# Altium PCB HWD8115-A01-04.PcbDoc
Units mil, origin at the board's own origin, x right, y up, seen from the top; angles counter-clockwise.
Board outline 1289.56 x 3691.13 mil, 2 copper layers (TopLayer, BottomLayer); 72 components, 55 nets, 228 pads, 384 vias.
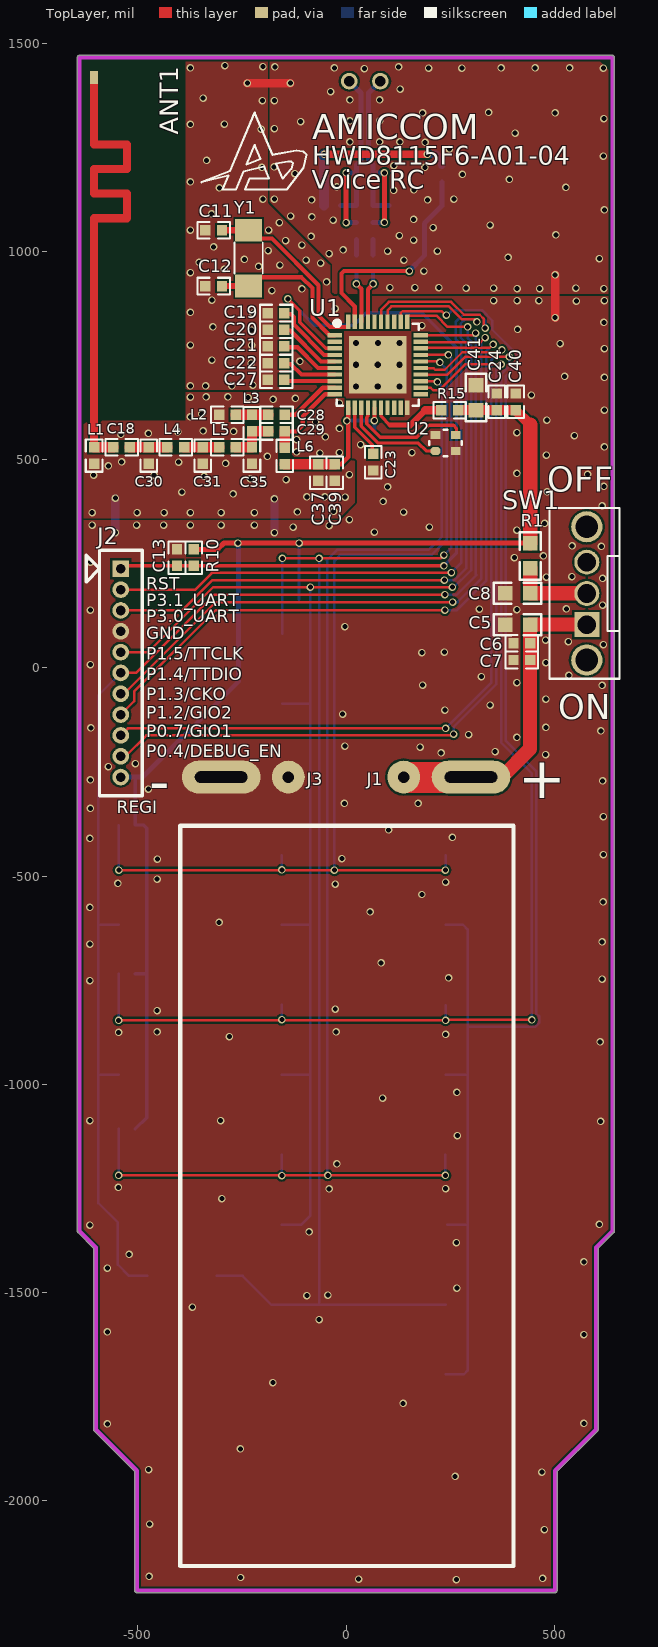
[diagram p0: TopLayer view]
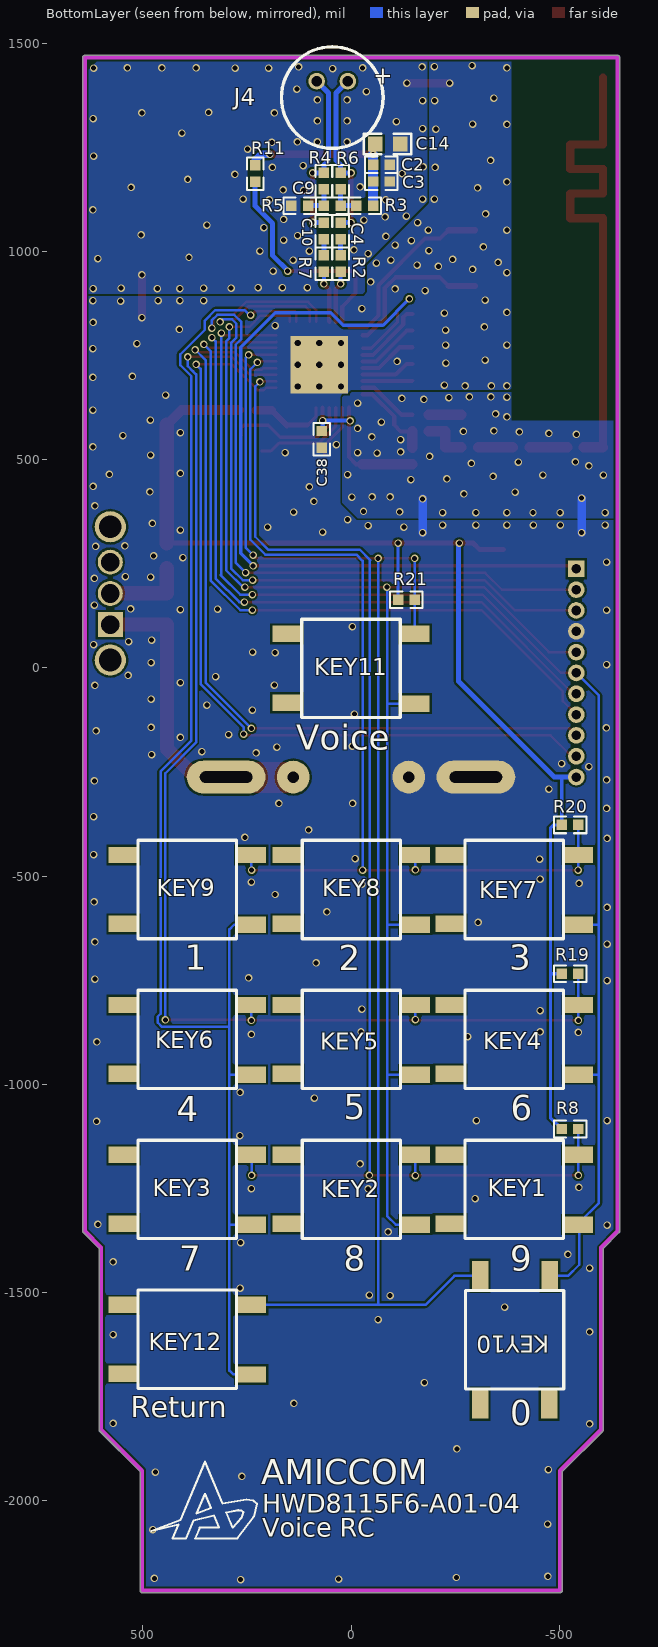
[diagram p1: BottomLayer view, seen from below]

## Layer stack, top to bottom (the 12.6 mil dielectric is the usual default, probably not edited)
TopSolder: solder mask 0.4, Solder Resist, Dk 3.5
TopLayer: signal copper 1.4
Dielectric1: dielectric 12.6, FR-4, Dk 4.8
BottomLayer: signal copper 1.4
BottomSolder: solder mask 0.4, Solder Resist, Dk 3.5

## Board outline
-507.38,-2215.27 -507.38,-1929.81 -604.33,-1832.85 -604.32,-1832.87 cw(c-600.79,-1829.3) -605.8,-1829.3 -605.8,-1393.74 -643.7,-1355.84 -643.69,-1355.85 cw(c-640.16,-1352.29) -645.17,-1352.29 -645.17,1465.83 cw(c-640.16,1465.83) -640.16,1470.85 639.37,1470.85 cw(c639.37,1465.83) 644.39,1465.83 644.39,1268.98 cw(c639.37,1268.98) 644.15,1267.46 cw(c639.37,1265.93) 644.39,1265.93 644.39,-1352.29 cw(c639.37,-1352.29) 642.9,-1355.85 642.92,-1355.84 605.01,-1393.74 605.01,-1829.3 cw(c600,-1829.3) 603.53,-1832.87 603.55,-1832.85 506.59,-1929.81 506.59,-2215.27 cw(c501.57,-2215.27) 501.57,-2220.28 -502.36,-2220.28 cw(c-502.36,-2215.27)

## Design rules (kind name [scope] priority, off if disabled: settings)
Clearance Clearance_2 [InNetClass('RF')] p1 off: gap=15
Clearance [All] p2 off: gap=8
Clearance Clearance_1 [All] p3: gap=5
ComponentClearance [All] p1 off: gap=10 collisioncheckmode=3 verticalgap=10 showdistances=FALSE
FabricationTestPointUsage TestPointUsage [All] p1: valid=0 allowmultiple=FALSE
FabricationTestpoint Testpoint [All] p1: side=3 testpointundercomponent=TRUE minsize=40 maxsize=100 preferedsize=60 minholesize=20 maxholesize=40 preferedholesize=32 testpointgrid=1 allowsidetop=TRUE allowsidebottom=TRUE usegrid=TRUE gridtolerance=0.01
HoleSize [All] p1: absolutevalues=TRUE maxlimit=200 minlimit=1 maxpercent=80.000 minpercent=20.000
PolygonConnect PolygonConnect_12 [All vs IsNamedPolygon('GND_B')] p1: connectstyle=Direct reliefconductorwidth=10 reliefentries=4 polygonreliefangle="90 Angle" airgapwidth=10
PolygonConnect PolygonConnect_11 [All vs IsNamedPolygon('BOTTOM-GND')] p2: connectstyle=Direct reliefconductorwidth=10 reliefentries=4 polygonreliefangle="90 Angle" airgapwidth=10
PolygonConnect PolygonConnect_10 [All vs IsNamedPolygon('TOP-GND')] p3: connectstyle=Direct reliefconductorwidth=10 reliefentries=4 polygonreliefangle="90 Angle" airgapwidth=10
PolygonConnect PolygonConnect_9 [All vs IsNamedPolygon('TOP-GND')] p4: connectstyle=Direct reliefconductorwidth=10 reliefentries=4 polygonreliefangle="90 Angle" airgapwidth=10
PolygonConnect PolygonConnect_8 [All vs IsNamedPolygon('TOP-GND')] p5: connectstyle=Direct reliefconductorwidth=10 reliefentries=4 polygonreliefangle="90 Angle" airgapwidth=10
PolygonConnect PolygonConnect_7 [All vs IsNamedPolygon('TOP-GND')] p6: connectstyle=Direct reliefconductorwidth=10 reliefentries=4 polygonreliefangle="90 Angle" airgapwidth=10
PolygonConnect PolygonConnect_6 [All vs IsNamedPolygon('BOTTOM-GND')] p7: connectstyle=Direct reliefconductorwidth=10 reliefentries=4 polygonreliefangle="90 Angle" airgapwidth=10
PolygonConnect PolygonConnect_5 [All vs IsNamedPolygon('TOP-GND')] p8: connectstyle=Direct reliefconductorwidth=10 reliefentries=4 polygonreliefangle="90 Angle" airgapwidth=10
PolygonConnect PolygonConnect_4 [All vs IsNamedPolygon('TOP-GND')] p9: connectstyle=Direct reliefconductorwidth=10 reliefentries=4 polygonreliefangle="90 Angle" airgapwidth=10
PolygonConnect PolygonConnect_3 [All vs IsNamedPolygon('TOP-GND')] p10: connectstyle=Relief reliefconductorwidth=10 reliefentries=4 polygonreliefangle="90 Angle" airgapwidth=10
PolygonConnect PolygonConnect_2 [All vs IsNamedPolygon('TOP-GND')] p11: connectstyle=Direct reliefconductorwidth=10 reliefentries=4 polygonreliefangle="90 Angle" airgapwidth=10
PolygonConnect PolygonConnect_1 [All vs IsNamedPolygon('TOP-GND')] p12: connectstyle=Direct reliefconductorwidth=10 reliefentries=4 polygonreliefangle="90 Angle" airgapwidth=10
PolygonConnect [All] p13: connectstyle=Direct reliefconductorwidth=10 reliefentries=4 polygonreliefangle="90 Angle" airgapwidth=10
RoutingVias [All] p1: holewidth=28 width=50 viastyle="Through Hole" minholewidth=10 minwidth=12 maxholewidth=28 maxwidth=50
SolderMaskExpansion [HasPad('*A')] p1: expansion=-30
Width [All] p1: maxlimit=100 minlimit=6 preferedwidth=25
26 further rules are at their usual default settings.

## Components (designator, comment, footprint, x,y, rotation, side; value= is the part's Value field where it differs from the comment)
ANT1 "ANTENNA" ANT_Bit -606,1436 r90 top
C2 "4.7nF" 0402 -53,1208 r180 bottom
C3 "4.7pF" 0402 -53,1168 r180 bottom
C4 "0.47uF" 0402 25,1029 r90 bottom
C5 "4.7uF" 0603 442,104 r180 top
C6 "4.7nF" 0402 442,59 r180 top
C7 "4.7pF" 0402 442,19 r180 top
C8 "4.7uF" 0603 442,179 r180 top
C9 "4.7uF" 0402 25,1110 r0 bottom
C10 "0.47uF" 0402 65,1029 r90 bottom
C11 "22pF" 0402 -298,1051 r180 top
C12 "22pF" 0402 -298,917 r180 top
C13 "1uF" 0402 -406,245 r90 top
C14 "4.7uF" 0603 -58,1258 r180 bottom
C18 "0R" 0402 -559,530 r0 top
C19 "1uF" 0402 -148,852 r180 top
C20 "1uF" 0402 -148,812 r180 top
C21 "330pF" 0402 -148,772 r180 top
C22 "120pF" 0402 -148,732 r180 top
C23 "0.5pF" 0402 65,514 r270 top
C24 "4.7nF" 0402 362,619 r90 top
C27 "1uF" 0402 -148,692 r180 top
C28 "3.3pF" 0402 -147,608 r180 top
C29 "22pF" 0402 -147,568 r180 top
C30 "NC" 0402 -474,490 r90 top
C31 "1.2pF" 0402 -344,490 r90 top
C35 "1pF" 0402 -226,530 r270 top
C37 "100pF" 0402 -67,489 r270 top
C38 "1uF" 0402 70,569 r270 bottom
C39 "0.1uF" 0402 -27,489 r270 top
C40 "4.7pF" 0402 407,619 r90 top
C41 "4.7uF" 0603 312,619 r90 top
J1 "BAT_V+" "BAT_PAD - duplicate1" 300,-262 r180 top locked
J2 "CON/11P 1.27" HDR11_1.27 -541,238 r270 top
J3 "BAT_GND" "BAT_PAD - duplicate1" -300,-262 r0 top
J4 "MICPHONE" "MIC PHONE" 45,1409 r0 bottom
KEY1 "KEY_PAD" SW-4 -510,-1370 r0 bottom
KEY2 "KEY_PAD" SW-4 -119,-1370 r0 bottom
KEY3 "KEY_PAD" SW-4 275,-1370 r0 bottom
KEY4 "KEY_PAD" SW-4 -510,-1010 r0 bottom
KEY5 "KEY_PAD" SW-4 -119,-1010 r0 bottom
KEY6 "KEY_PAD" SW-4 275,-1010 r0 bottom
KEY7 "KEY_PAD" SW-4 -510,-650 r0 bottom
KEY8 "KEY_PAD" SW-4 -119,-650 r0 bottom
KEY9 "KEY_PAD" SW-4 275,-650 r0 bottom
KEY10 "KEY_PAD" SW-4 -511,-1495 r270 bottom
KEY11 "KEY_PAD" SW-4 -118,-119 r0 bottom
KEY12 "KEY_PAD" SW-4 275,-1730 r0 bottom
L1 "NC" 0402 -605,530 r270 top
L2 "1.8nH" 0402 -265,608 r180 top
L3 "3.9nH" 0402 -226,568 r90 top
L4 "1.8nH" 0402 -429,530 r0 top
L5 "3.3nH" 0402 -305,530 r0 top
L6 "NC" 0402 -147,489 r90 top
R1 "0R" 0603 442,299 r270 top
R2 "0R" 0402 25,951 r90 bottom
R3 "1K" 0402 -53,1110 r0 bottom
R4 "4.7K" 0402 25,1149 r90 bottom
R5 "1K" 0402 143,1110 r180 bottom
R6 "4.7K" 0402 65,1149 r90 bottom
R7 "0R" 0402 65,951 r90 bottom
R8 "10K" 0402 -506,-1107 r180 bottom
R10 "100K" 0402 -366,285 r270 top
R11 "2K" 0402 230,1207 r270 bottom
R15 "0R" 0402 269,619 r180 top
R19 "10K" 0402 -506,-734 r180 bottom
R20 "10K" 0402 -506,-377 r180 bottom
R21 "10K" 0402 -113,164 r180 bottom
SW1 "SW DIP-3P-180" SW3-2 578,104 r270 top
U1 "" A8153 76,728 r0 top
U2 "CRYSTAL/2.0*1.6" XTAL_2.0*1.6 216,521 r0 top
Y1 "32.768KHz, CL=12.5pF" XTAL\32.768K\SMD -234,1051 r270 top

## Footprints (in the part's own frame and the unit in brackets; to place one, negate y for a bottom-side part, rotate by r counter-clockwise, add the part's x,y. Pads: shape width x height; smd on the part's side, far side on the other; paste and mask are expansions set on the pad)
0402 [mil]
  rect 25x25 smd: 1(0,0) 2(40,0)
  silkscreen extent -19,-20 59,20
0603 [mil]
  rect 35x35 smd: 1(0,0) 2(60,0)
  silkscreen extent -27,-25 87,25
A8153 [mm]
  rect 0.889x0.26 smd: 1(-2.627,1.8) 2(-2.627,1.4) 3(-2.627,1) 4(-2.627,0.6) 5(-2.627,0.2) 6(-2.627,-0.2) 7(-2.627,-0.6) 8(-2.627,-1) 9(-2.627,-1.4) 10(-2.627,-1.8) 21(2.627,-1.8) 22(2.627,-1.4) 23(2.627,-1) 24(2.627,-0.6) 25(2.627,-0.2) 26(2.627,0.2) 27(2.627,0.6) 28(2.627,1) 29(2.627,1.4) 30(2.627,1.8)
  rect 0.26x0.889 smd: 11(-1.8,-2.627) 12(-1.4,-2.627) 13(-1,-2.627) 14(-0.6,-2.627) 15(-0.2,-2.627) 16(0.2,-2.627) 17(0.6,-2.627) 18(1,-2.627) 19(1.4,-2.627) 20(1.8,-2.627) 31(1.8,2.627) 32(1.4,2.627) 33(1,2.627) 34(0.6,2.627) 35(0.2,2.627) 36(-0.2,2.627) 37(-0.6,2.627) 38(-1,2.627) 39(-1.4,2.627) 40(-1.8,2.627)
  round 0.381 hole 0.381: ""(-1.321,-1.321) ""(-1.321,0) ""(-1.321,1.321) ""(0,-1.321) ""(0.013,1.321) ""(1.321,-1.321) ""(1.321,0) ""(1.321,1.321)
  rect 3.5x3.5 hole 0.381: ""(0,0)
  silkscreen extent -2.52,-2.5 2.5,2.57
ANT_Bit [mm]
  rect 0.8x0.5 smd: 1(-0.474,-0.025)
"BAT_PAD - duplicate1" [mm]
  oval 4.8x2 hole 0.7 slot 3.2 at 0 deg: 1(0,0)
  round 2 hole 0.7: 2(4.1,0)
HDR11_1.27 [mil]
  rect 40x40 hole 23: 1(0,0)
  round 40 hole 23: 2(50,0) 3(100,0) 4(150,0) 5(200,0) 6(250,0) 7(300,0) 8(350,0) 9(400,0) 10(450,0) 11(500,0)
  silkscreen extent -45,-51 545,51
"MIC PHONE" [mil]
  round 40 hole 25: 1(-37.4,0) 2(37.4,0)
  silkscreen extent -122,-83 122,161
SW3-2 [mil]
  rect 60x60 hole 45: 1(0,0)
  round 60 hole 45: 2(-75,0) 3(-150,0)
  round 75 hole 55: ""(-235,0) ""(85,0)
  silkscreen extent -280,-90 130,79
SW-4 [mm]
  rect 1.8x1 smd: 1(-0.9,-0.85) 2(-0.9,-5.1) 3(6.9,-5.1) 4(6.9,-0.9)
  silkscreen extent 0,-6 6,0
XTAL\32.768K\SMD [mil]
  rect 55.12x65 smd: 1(0,0) 2(133.69,0.09)
  silkscreen extent 29,-34 105,34
XTAL_2.0*1.6 [mm]
  oct 0.6x0.47 smd: 1(-0.038,-0.001)
  rect 0.6x0.47 smd: 2(1.202,-0.001) 3(1.202,0.969) 4(-0.038,0.969)
  silkscreen extent -0.42,-0.32 1.58,1.28

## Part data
C2 C3 C4 C5 C6 C7 C8 C9 C10 C14 C18 C19 C20 C21 C22 C23 C24 C27 C28 C29 C30 C31 C35 C37 C38 C39 C40 C41: library part CAP
C11 C12: library part C/0603, "Chip C"
C13: library part C/0402, "Chip C"
J1 J3: library part BAT_PAD
J2: "Hole 23mil"
L1 L2 L3 L4 L5 L6: library part L/0402, "Chip L"
R1 R8 R19 R20 R21: library part RES1
R2 R3 R4 R5 R6 R7 R10 R11 R15: library part R/0603, "Chip  R"
U1: library part A8115
U2: library part CRYSTAL/5*3.2
Y1: library part CRYSTAL, "Crystal"

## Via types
v1: diameter 18, hole 12, TopLayer to BottomLayer, 384 vias

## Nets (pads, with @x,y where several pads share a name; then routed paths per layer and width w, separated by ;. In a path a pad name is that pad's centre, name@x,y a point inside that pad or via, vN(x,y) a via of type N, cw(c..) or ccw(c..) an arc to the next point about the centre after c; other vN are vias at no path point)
AGND: C2.2 C3.2 C14.2 R5.1
  other v1: 411,911 465,911 619,911 288,912 354,912 552,912 105,913 165,913 223,913 502,944 187,953 139,979 608,983 389,986 -40.99,995 100,1001 219,1001 -7,1004 162,1027 -84,1036 128,1038 504,1040 209,1057 346,1063 -31,1075 162,1077 -82,1083 -133,1085 620,1100 -83,1124 196,1124 -172,1126 259,1126 114,1147 163,1148 528,1154 -22,1155 392,1173 279,1185 -123,1187 189,1202 -173,1203 115,1206 618,1229 248,1246 190,1262 9.09,1263 80.71,1263 129,1263 406,1284 -172,1295 -109,1312 9.09,1313.47 80.71,1313.47 619,1319 184,1333 502,1333 342,1334 -172,1362 9.09,1364 80.71,1364 -37,1384 130,1390 -134,1404 44,1439 198,1440 278,1440 618,1440 -28,1441 372,1441 454,1441 537,1441 -171,1443 126,1443
BPBG: C21.1 U1.6 | length 141.2
  TopLayer w10: C21.1@-148,770 -117,770 -67.13,720.13 U1.6
DGND: C30.1 C31.1 C35.2 C37.2 C39.2 L1.2 L2.2
  other v1: -610,373 -502,373 -437,373 -374,373 -300,373 -220,373 -117,375 -30,376 -172,406 -554,408 -2,410 -94,411 -51,411 -271,418 -394,422 -144,452 -230,454 -341,460 -606,463 -461,463 8,464 -571,485 -289,491 -402,494 -539,495 -189,508 -63,516 -16,517 -119,519 -119,548 -50,555 -541,561 -475,563 -404,567 -270,568 -343,569 -16,575 -73,590 -374.02,603 -347,610 -16,636 -175,645 -122,647 -235,649 -374.02,650 -336,651 -284,651
GND: C5.2 C6.2 C7.2 C8.2 C11.2 C12.2 C13.2 C19.2 C20.2 C21.2 C22.2 C23.2 C24.2 C27.2 C38.2 C40.2 C41.2 J2.4 J3.1 J3.2 U1. U1.20 U2.2 U2.4 | length 370
  TopLayer w20: v1(-237,1404) -134,1404 ; v1(502,841) 502,944
  BottomLayer w20: v1(-554,325) -554,408 ; v1(-172,325) -172,406
  other v1: 265,-2189 30,-2188 472,-2186 -253,-2184 -473,-2181 476,-2069 -472,-2056 262,-1941 470,-1931 -474,-1925 -254,-1875 -573,-1815 571,-1814 137,-1766 -176,-1716 571,-1601 -573,-1594 -65,-1565 -369,-1535 -94,-1507 -44,-1506 266,-1489 -573,-1441 571,-1426 -521,-1408 265,-1380 -89,-1354 -615,-1338 608,-1336 -298,-1274 -41,-1251 239,-1250 -547,-1247 -22,-1191 267,-1123 611,-1089 -615,-1087 -301,-1087 88,-1033 266,-1019 610,-898 -280,-885 239,-880 -546,-875 -454,-874 -24,-874 -454,-823 -26,-819 -615,-751 615,-747 246,-744 84,-708 -615,-663 615,-658 -305,-611 58,-586 -615,-575 617,-562 182,-544 -26,-519 -548,-517 239,-514 -454,-507 -453,-459 -10,-458 618,-448 -615,-409 255,-407 102,-389 618,-357 -614,-337 -4,-325 173,-325 -475,-291 616,-271 -614,-269 -571,-237 -506,-230 479,-208 228,-204 358,-201 178,-190 -3,-188 410,-167 294,-160 612,-151 -613,-144 480,-143 -8,-111 237,-101 346,-89 480,-75 615,-42 184,-41 410,-35 325,-21 535,-18 -614,8 480,13 182,37 236,38 618,56 534,63 479,67 -3,99 -614,139 410,140 320,141 529,142 616,151 616,215 481,218 542,219 -614,254 404,265 474,269 613,292 543,293 68,326 410,331 -127,338 200,338 -41,342 -610,343 -503,343 -438,343 -374,343 -300,343 -220,343 477,347 8,356 138,374 615,389 89,400 483,423 100,435 619,436 580,465 410,467 481,511 158,517 620,531 35,536 548,558 410,565 482,595 620,619 445,655 -374.02,677 -337,677 -274,677 -224,679 620,698 525,700 -228,732 -111,736 -322,739 620,767 -374.02,775 -227,775 514,779 -227,811 412,813 -320,819 182,822 619,830 -224,852 -374.02,854 -26,863 553,881 354,882 411,882 463,882 620,882 -322,883 -178,906 -106,910 -47,927 -374.02,949 -292,957 -210,964 -159,967 -61,972 -353,974 -96,979 -244,981 -187,1002 -318,1011 -106,1015 -145,1026 -374,1051 -186,1051 -160,1069 -323,1090 -200,1126 -304,1153 -374.02,1167 -202,1202 -335,1219 -204,1294 -374.02,1305 -292,1306 -201,1362 -343,1368 -374.02,1441 -200,1444 -291,1446
MBIAS: C2.1 C3.1 C14.1 R3.1 R11.1 | length 423.8
  TopLayer w18: v1(-53,1233) v1(195,1233)
  BottomLayer w18: v1(195,1233) 216,1233 230,1219 R11.1
  BottomLayer w24: R3.1 -53,1163 v1(-53,1233)
NetC4_1: C4.1 R2.2 | length 38
  BottomLayer w12: R2.2 C4.1
NetC4_2: C4.2 J4.1 R4.2 | length 406.3
  TopLayer w12: v1(0,1069) v1(0,1189)
  BottomLayer w12: v1(0,1069) C4.2 ; v1(0,1189) R4.2 25,1208 36,1219 36,1380.6 J4.1
NetC8_1: C8.1 R1.2 SW1.2 | length 196
  TopLayer w35: R1.2 C8.1 SW1.2
NetC9_1: C9.1 R3.2 R4.1 | length 77
  BottomLayer w12: R3.2 C9.1 R4.1
NetC9_2: C9.2 R5.2 R6.1 | length 77
  BottomLayer w12: R6.1 C9.2 R5.2
NetC10_1: C10.1 R7.2 | length 38
  BottomLayer w12: R7.2 C10.1
NetC10_2: C10.2 J4.2 R6.2 | length 409.7
  TopLayer w12: v1(92,1070) v1(92,1189)
  BottomLayer w12: C10.2 66,1070 v1(92,1070) ; J4.2 54,1380.6 54,1219 65,1208 R6.2 v1(92,1189)
NetC18_2: C18.2 C30.2 L4.1 | length 90
  TopLayer w25: C18.2 -462,530 L4.1
NetC23_1: C23.1 U1.12 | length 128
  TopLayer w8: U1.12 20.88,578.12 63,536 C23.1@63,514
NetC28_2: C28.2 L2.1 L3.2 | length 78
  TopLayer w25: L2.1 L3.2 C28.2
NetC29_2: C29.2 C35.1 L3.1 L5.2 | length 116
  TopLayer w25: L5.2 C35.1 L3.1 C29.2
NetC31_2: C31.2 L4.2 L5.1 | length 84
  TopLayer w25: L4.2 C31.2 L5.1
NetR15_2: R15.2 U1.16 | length 189.2
  TopLayer w8: U1.16 83.87,604.13 105,583
  TopLayer w12: 105,583 154,583
  TopLayer w15: 154,583 190,619
  TopLayer w20: 190,619 R15.2
P0_0: U1.17
P0_1: U1.18
P0_2: U1.19
P0_3: U1.21
P0_4/DEBUG_EN: J2.10 U1.22 | length 1976.9
  TopLayer w6: J2.10 -529.44,-212 -479.44,-162 255,-162 v1(258,-159) ; U1.22 203.12,672.88 209,667 224,667 286,729 v1(372,729)
  BottomLayer w6: v1(258,-159) 258,-142 361,-39 361,718 v1(372,729)
P0_7/GIO1: J2.9 U1.25 | length 1968.1
  TopLayer w6: J2.9 -524,-145 v1(239,-145) ; U1.25 209.87,720.13 214,716 237,716 279,758 368,758 v1(374,764)
  BottomLayer w6: v1(239,-145) 349,-35 349,739 v1(374,764)
P1_2/GIO2: J2.8 U1.28 | length 1779.9
  TopLayer w6: J2.8 -509,-80 -509,-57 -313,139 v1(237,139) ; U1.28@179.43,769 345,769 v1(353,777) v1@353,772.5
  BottomLayer w6: v1(237,139) 266,139 337,210 337,761 v1(353,777)
P1_3/CKO: J2.7 U1.29 | length 1714.7
  TopLayer w6: J2.7@-533,-62 -313,158 v1(256,158) ; U1.29 179.43,782 323,782 v1(334,793)
  BottomLayer w6: v1(256,158) 268,158 325,215 325,784 v1(334,793)
P1_7: U1.33
P3_0_UART: J2.3 U1.34 | length 1770.1
  TopLayer w6: J2.3 -394,138 -321,211 v1(236,211) ; U1.34 99.62,858.62 109,868 247,868 278.27,836.73 308.27,836.73 v1(314,831)
  BottomLayer w6: v1(236,211) 260,211 288,239 288,780.56 275,793.56 275,826.52 285.21,836.73 308.27,836.73 v1(314,831)
P3_1_UART: J2.2 U1.35 | length 1854.2
  TopLayer w6: J2.2 -362,188 -322,228 252,228 v1(253,229) ; U1.35 83.87,859.87 103,879 252,879 283,848 321.04,848 331,838.04 331,819 v1(334,816)
  BottomLayer w6: v1(253,229) 277,253 277,776 263.21,789.79 263.21,830.29 280.93,848 321.04,848 334,835.04 v1(334,816)
P3_2: U1.36
P3_3_ADC_N: R7.1 U1.37 | length 124.8
  TopLayer w10: U1.37 52.38,909.38 v1(65,922)
  BottomLayer w10: v1(65,922) R7.1
P3_4_ADC_P: R2.1 U1.38 | length 123.4
  TopLayer w10: v1(25,922) 36.63,910.37 ; U1.38 36.63,909.38
  BottomLayer w10: v1(25,922) R2.1
P3_5_MICVDD: R11.2 U1.39 | length 542
  TopLayer w10: U1.39 20.88,868.12 -11,900 -11,947 -5,953 v1(152,953)
  BottomLayer w12: v1(152,953) 151,953 188,990 188,1067 230,1109 R11.2
PCB_ANT: ANT1.1 C18.1 L1.1 | length 1248.2
  TopLayer w19.68: L1.1 -605,1080 -526.26,1080 -526.26,1139.06 -605,1139.06 ; ANT1.1 -605,1257.05 -526.26,1257.05 -526.26,1198 ; -604.94,1139.06 -604.94,1198 ; -604.94,1198.11 -526.26,1198.11
  TopLayer w25: L1.1 C18.1
REGI: C24.1 C40.1 C41.1 J2.11 R1.1 R8.1 R10.1 R15.1 R19.1 R20.1 R21.1 | length 3043.5
  TopLayer w8: 438,353 440,351 442,353
  TopLayer w12: R10.1 -308,285 -293,300 v1(-260,300) v1(-113,300) 441,300 R1.1
  TopLayer w24: R15.1 C41.1 C24.1 C40.1 442,584
  TopLayer w35: R1.1 442,353 442,584
  BottomLayer w8: R8.1 -479,-1080 -479,-385 -487,-377 R20.1 -506,-262 ; R19.1 -480,-734 ; R21.1 v1(-113,300)
  BottomLayer w12: J2.11 -506,-262 -488,-262 -258,-32 v1@-258,300
RFI: C28.1 U1.9 | length 146.4
  TopLayer w10: C28.1 -121,608 -56.12,672.88 U1.9
RFO: C29.1 L6.2 U1.10 | length 207.4
  TopLayer w10: C29.1 -119,568 -104,583 -104,603.27 -50.13,657.13 U1.10
  TopLayer w25: L6.2 C29.1
RST: C13.1 J2.1 R10.2 U1.3 | length 1971.9
  TopLayer w8: J2.1 -534,245 C13.1 R10.2 v1(235,245) ; v1(-140,886) -111.5,857.5 -111.5,830.3 -48.57,767.37 U1.3
  BottomLayer w8: v1(-140,886) -77,823 19,823 49,853 182,853 265,770 265,275 v1(235,245)
RTCI: C11.1 U1.40 Y1.1 | length 440.7
  TopLayer w10: Y1.1 -214,1031 -178,1031 -66,919 -66,846.21 -38.79,819 U1.40@4,819
  TopLayer w15: C11.1 Y1.1
RTCO: C12.1 U1.1 Y1.2 | length 379.1
  TopLayer w10: Y1.2 -213.22,938 -107,938 -81,912 -81,840 -39.87,798.87 U1.1
  TopLayer w15: C12.1 -234.22,917 Y1.2
V_BAT: C5.1 C6.1 C7.1 J1.1 J1.2 SW1.1 | length 765.6
  TopLayer w34: J1.1 374,-262 442,-194 442,-9 442,48 C5.1 SW1.1
  TopLayer w75: J1.2@138.58,-263 J1.1@300,-263
VDD_ADC: C27.1 U1.8 | length 121.1
  TopLayer w8: C27.1@-148,690 C27.1@-146.63,688.63
  TopLayer w10: C27.1@-146.63,688.63 U1.8
VDD_FH: C19.1 U1.4 | length 171.9
  TopLayer w10: C19.1@-148,850 -133,850 -125.5,842.5 -125.5,824.5 -52.62,751.62 U1.4
VDD_P: C37.1 C38.1 C39.1 L6.1 U1.11 U1.15 | length 399.7
  TopLayer w10: C39.1 -12,489 5.13,506.13 U1.11 ; v1(68,594) 68,596 68.13,596.13 U1.15
  TopLayer w25: L6.1 -107,489 C37.1 C39.1
  BottomLayer w10: v1(2,593) 3,594 v1(68,594) C38.1@68,569
VDD_S: C20.1 U1.5 | length 151.3
  TopLayer w10: C20.1@-148,810 -134,810 -59.87,735.87 U1.5
VREF: C22.1 U1.7 | length 131.2
  TopLayer w10: C22.1@-148,730 -133,730 -107.38,704.38 U1.7
X1_P0_5: KEY1.2 KEY2.2 KEY3.2 R8.2 U1.23 | length 3189.9
  TopLayer w6: v1(-546,-1218.65) v1@-154.43,-1218.65 ; v1(-154.43,-1219.21) v1@-154.43,-1218.65 ; U1.23 217.37,688.63 v1(219,687) ; v1@238.57,-1218.65 v1(-44,-1218.65) v1@-154.43,-1218.65
  BottomLayer w6: v1(-546,-1218.65) R8.2 ; v1@-154.43,-1218.65 KEY2.2 ; v1(-44,-1218.65) -45,-1217.65 -45,258 -46,259 -21,284 199,284 230,315 230,676 v1(219,687) ; v1(238.57,-1218.43) KEY3.2@238.57,-1169.21
X2_P0_6: KEY4.2 KEY5.2 KEY6.2 R19.2 U1.24 | length 3035.3
  TopLayer w6: v1(-546,-846) v1(239,-846) ; U1.24 243.38,704.38 286,747 v1(392,747) ; v1@240,-845 v1(446,-845)
  BottomLayer w6: v1(-546,-846) -545.43,-845.43 KEY4.2 ; KEY4.2@-546,-808.65 R19.2 ; v1(-154.43,-844.43) KEY5.2 ; v1(239,-846) KEY6.2@239,-809.78 ; 379,712 372,705 372,-179 446,-253 v1(446,-845) ; 379.04,712 392,724.96 v1(392,747)
X3_P1_0: KEY7.2 KEY8.2 KEY9.2 R20.2 U1.26 | length 2479.9
  TopLayer w6: v1(-545.43,-485.43) v1(238.43,-485.43) ; U1.26 223.13,735.87 v1(225,734)
  BottomLayer w6: v1(-545.43,-485.43) KEY7.2 R20.2@-545.43,-377.57 ; v1(-154.43,-484.87) KEY8.2 ; v1(-28,-485.43) -28,257 -13,272 206,272 242,308 242,717 v1(225,734) v1@227,736 ; v1(238.43,-485.43) 239.57,-484.3 KEY9.2
X4_P1_1: KEY10.2 KEY11.2 KEY12.2 R21.2 U1.27 | length 3499.3
  TopLayer w6: v1(-153,263) v1(-65,263) 227,263 v1(235,271) ; U1.27 v1(245.62,751.62)
  BottomLayer w6: KEY10.2 -248.43,-1459.57 -178.79,-1529.21 KEY12.2 ; KEY11.2@-153,82.22 R21.2 v1(-153,263) ; -65,-1528.21 v1(-65,263) ; v1(235,271) 253,289 253,744.24 v1(245.62,751.62)
XI: U1.13 U2.1 | length 246.5
  TopLayer w8: U1.13 36.63,580.75 77.38,540 173,540 192.05,520.95 U2.1
XO: U1.14 U2.3 | length 300.4
  TopLayer w8: U1.14 52.38,603.83 50,601.46 50,585.77 81.77,554 170,554 199,583 258,583 265,576 265,560.82 U2.3
Y1_P1_4/TTDIO: J2.6 KEY1.1 KEY4.1 KEY7.1 KEY10.1 U1.30 | length 3309.8
  TopLayer w6: J2.6 -503.97,-12 -315.97,176 v1(237,176) ; U1.30 305.87,798.87 v1(311,804)
  BottomLayer w6: -595,-616.54 KEY7.1 ; -594.46,-976.54 KEY4.1 ; J2.6 -595,-66 -595,-1285 -548,-1332 -548,-1433 -521.43,-1459.57 KEY10.1 ; v1(237,176) 266,176 313,223 311,225 v1(311,804)
Y2_P1_5/TTCLK: J2.5 KEY2.1 KEY5.1 KEY8.1 KEY11.1 U1.31 | length 3465.9
  TopLayer w6: J2.5 -475,38 -319,194 v1(255,194) ; U1.31 146.87,846 216.98,846 243.98,819 v1(292,819)
  BottomLayer w6: KEY2.1 -107.54,-1336.54 -86.61,-1315.61 -86.61,-85.54 ; KEY5.1 -87.15,-976.54 ; KEY8.1 -87.15,-616.54 ; KEY11.1 -86.61,-85.54 ; v1@-86.61,194 -86.61,-85.54 ; v1@258.21,192.73 300,234.52 300,784.11 292,792.11 v1(292,819)
  other v1: -86,194
Y3_P1_6: KEY3.1 KEY6.1 KEY9.1 KEY12.1 U1.32 | length 3469.8
  TopLayer w6: U1.32 131.12,852.12 136,857 229,857 239,847 v1(241,847)
  BottomLayer w6: KEY12.1 282.46,-1696.54 292,-1687 292,-628 280.54,-616.54 KEY9.1 ; KEY6.1 291.54,-976.54 ; v1(241,847) 241,844 256,859 326,859 351,834 351,812.04 410,753.04 410,727.4 383,700.4 383,-174.44 457,-248.44 457,-830.34 464,-837.34 464,-851.48 453.48,-862 292,-862 ; KEY3.1@242.57,-1336.54 290.54,-1336.54
pads on no net: KEY1.3 KEY1.4 KEY2.3 KEY2.4 KEY3.3 KEY3.4 KEY4.3 KEY4.4 KEY5.3 KEY5.4 KEY6.3 KEY6.4 KEY7.3 KEY7.4 KEY8.3 KEY8.4 KEY9.3 KEY9.4 KEY10.3 KEY10.4 KEY11.3 KEY11.4 KEY12.3 KEY12.4 SW1. SW1.3 U1.2

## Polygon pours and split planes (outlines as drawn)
GND on BottomLayer "GND_B" (solid, remove dead copper, pour order 12): -693,1507 689,1507 695,1513 724,1484 724,-2307 -664,-2307 -693,-2278
DGND on BottomLayer "B" (solid, remove dead copper, pour order 10): -6,662 -640.16,662 -640.16,456.69 -640,360 -16,360 19,395 21,397 21,568 21,650 8,663
AGND on BottomLayer "AGND_B" (solid, remove dead copper, pour order 8): -183,1465.83 -183,1119 -40,976 -33,969 -33,898 639.37,898 639.37,1426.46 600,1465.83
GND on TopLayer "GND_T" (solid, remove dead copper, pour order 11): -692,1506 690,1506 696,1512 725,1483 725,-2308 -663,-2308 -692,-2279
DGND on TopLayer "RFGND_T" (solid, remove dead copper, pour order 9): -6,662 -640.16,662 -640.16,456.69 -640,360 -16,360 19,395 21,397 21,568 21,650 8,663
AGND on TopLayer "AGND_T" (solid, remove dead copper, pour order 7): -183,1465.83 -183,1119 -40,976 -33,969 -33,898 639.37,898 639.37,1426.46 600,1465.83

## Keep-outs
KeepOutLayer:
  lines w10: 639.37,1265.93 639.37,902.21 639.37,456.69 639.37,-284.1 639.37,-729.61 639.37,-1352.29 600,-1391.66 600,-1829.3 501.57,-1927.73 501.57,-2215.27 -502.36,-2215.27 -502.36,-1964.27 -502.36,-1927.73 -600.79,-1829.3 -600.79,-1391.66 -640.16,-1352.29 -640.16,-729.61 -640.16,-284.1 -640.16,456.69 -640.16,902.21 -640.16,1267.98 -640.16,1465.83 639.37,1465.83 639.37,1268.98

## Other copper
TopLayer:
  pour cut-out: -385,593 -385,1465.83 -640.16,1465.83 -640.16,593
BottomLayer:
  pour cut-out: -640.16,593 -640.16,1466 -385,1466 -385,593

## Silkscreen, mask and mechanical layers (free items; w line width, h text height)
TopOverlay:
  lines w5: -347.55,1166.3 -282.83,1182.58 -297,1149 -264.49,1149 -246.47,1191.73 -197.46,1204.05 -185.14,1174.83 -231.61,1174.83 -242.51,1149 -141.73,1149 -101.96,1200.98 -94.56,1232.18 -103,1239.99 -119.52,1242.61 -176.86,1232.26 -219.37,1333.02 -278.27,1193.41 -347.55,1166.3 ; -239.33,1208.64 -205.06,1222.05 -219.37,1255.97 -239.33,1208.64 ; -168.09,1211.48 -152.63,1174.83 -131.55,1198.17 -127.1,1212.05 -131.11,1215.45 -139.28,1216.49 -168.09,1211.48
  lines w8: -624,206.18 -592.18,238 -592.18,239.18 -624,271 -624,206.18
  lines w10: -398,-2156 -398,-379 402,-379 402,-2156 -398,-2156
  text "AMICCOM" at -81,1269 h60
  text "HWD8115F6-A01-04" at -81,1208 h45
  text "Voice RC" at -82,1151 h45
  text "OFF" at 483,423 h60
  text "RST" at -480,188 h30
  text "P3.1_UART" at -480,148.43 h30
  text "P3.0_UART" at -480,110 h30
  text "GND" at -480,69 h30
  text "P1.5/TTCLK" at -480,19.98 h30
  text "P1.4/TTDIO" at -480,-30.02 h30
  text "P1.3/CKO" at -480,-78 h30
  text "P1.2/GIO2" at -480,-122 h30
  text "ON" at 510,-123 h60
  text "P0.7/GIO1" at -480,-166 h30
  text "P0.4/DEBUG_EN" at -480,-215 h30
  text "+" at 414,-313 h100
  text "-" at -473,-321 h100
  text "REGI" at -551,-349 h30
BottomOverlay:
  lines w5: 226.05,-2006.82 234.49,-1999.01 251.02,-1996.39 308.35,-2006.74 350.86,-1905.98 409.76,-2045.59 479.05,-2072.7 414.33,-2056.42 428.49,-2090 395.99,-2090 377.96,-2047.27 328.96,-2034.95 316.63,-2064.17 363.1,-2064.17 374,-2090 273.23,-2090 233.46,-2038.02 226.05,-2006.82 ; 258.6,-2026.95 262.61,-2023.55 270.78,-2022.51 299.59,-2027.52 284.13,-2064.17 263.05,-2040.83 258.6,-2026.95 ; 336.55,-2016.95 350.86,-1983.03 370.83,-2030.36 336.55,-2016.95
  text "Voice" at 131,-196 h60
  text "3" at -380,-725 h60
  text "1" at 399,-725 h60
  text "2" at 29,-726 h60
  text "5" at 18,-1084 h60
  text "6" at -384,-1086 h60
  text "4" at 419,-1088 h60
  text "9" at -382,-1447 h60
  text "8" at 17,-1447 h60
  text "7" at 413,-1448 h60
  text "Return" at 529,-1799 h50
  text "0" at -382,-1818 h60
  text "AMICCOM" at 215,-1960 h60
  text "HWD8115F6-A01-04" at 213,-2028 h45
  text "Voice RC" at 213,-2086 h45
TopSolder:
  rectangle: -615,593 -595,1070
  rectangle: -615,1070 -536,1090
  rectangle: -536,1070 -516,1129
  rectangle: -595,1129 -516,1149
  rectangle: -615,1129 -595,1208
  rectangle: -595,1188 -537,1208
  rectangle: -537,1188 -516,1247
  rectangle: -593,1247 -516,1267
  rectangle: -617,1247 -593,1437
  region: -152,1388 -152,1421 -219,1421 -219,1388
  rectangle: 487,860 520,927
BottomSolder:
  rectangle: -570,323 -537,390
  rectangle: -188,324 -155,391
